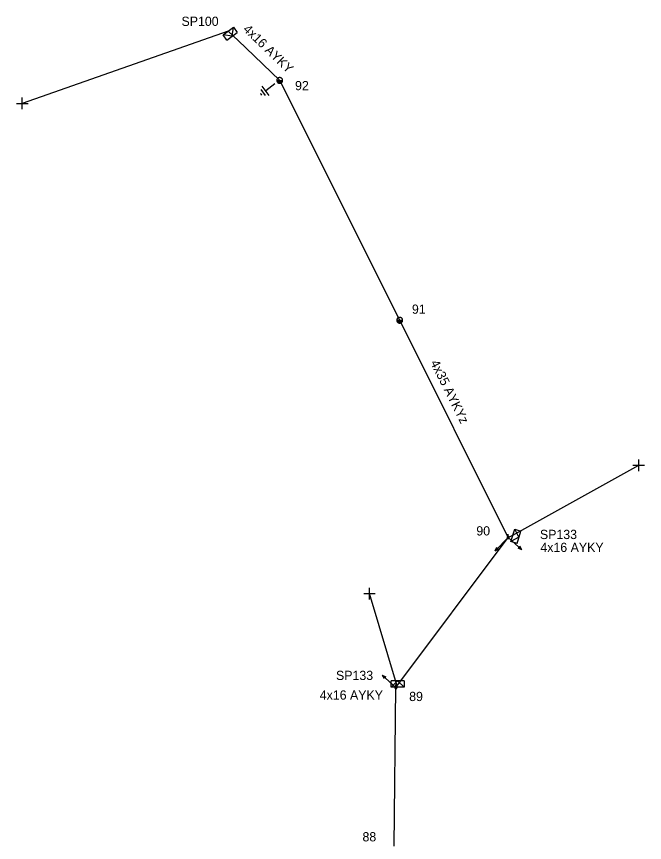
# Model space of a CAD drawing. Extents: x -788458 to -786145, y -1154772 to -1152372.
# Drawn here: x -787205.1 to -787137.1, y -1152461.7 to -1152372.4 of the extents above; entities that cross this region are included whole.
import ezdxf

# ---------------------------------------------------------------- set-up
doc = ezdxf.new("R2010")
doc.units = 0
for name, color, linetype in [('Vrstva 1', 7, 'Continuous'), ('Vrstva 13', 7, 'Continuous'), ('Vrstva 14', 7, 'Continuous'), ('Vrstva 15', 7, 'Continuous'), ('Vrstva 2', 7, 'Continuous'), ('Vrstva 31', 7, 'Continuous'), ('Vrstva 33', 7, 'Continuous'), ('Vrstva 34', 7, 'Continuous'), ('Vrstva 52', 7, 'Continuous'), ('Vrstva 53', 7, 'Continuous'), ('Vrstva 54', 7, 'Continuous'), ('Vrstva 59', 7, 'Continuous'), ('Vrstva 9', 7, 'Continuous')]:
    doc.layers.add(name, color=color, linetype=linetype)

# ---------------------------------------------------------------- blocks, each defined once
blk = doc.blocks.new('NN440')
at = {"layer": 'Vrstva 2'}
for points in [[(0.63, 0), (0.63, 0.06), (0.62, 0.13), (0.6, 0.19), (0.58, 0.25), (0.55, 0.31), (0.51, 0.37), (0.47, 0.42), (0.42, 0.46), (0.37, 0.51), (0.32, 0.54), (0.26, 0.57), (0.2, 0.59), (0.13, 0.61), (0.07, 0.62), (0, 0.63), (-0.06, 0.62), (-0.13, 0.61), (-0.19, 0.59), (-0.26, 0.57), (-0.31, 0.54), (-0.37, 0.51), (-0.42, 0.46), (-0.47, 0.42), (-0.51, 0.37), (-0.54, 0.31), (-0.57, 0.25), (-0.6, 0.19), (-0.62, 0.13), (-0.63, 0.06), (-0.63, 0), (-0.63, -0.07), (-0.62, -0.14), (-0.6, -0.2), (-0.57, -0.26), (-0.54, -0.32), (-0.51, -0.37), (-0.47, -0.43), (-0.42, -0.47), (-0.37, -0.51), (-0.31, -0.55), (-0.26, -0.58), (-0.19, -0.6), (-0.13, -0.62), (-0.06, -0.63), (0, -0.63), (0.07, -0.63), (0.13, -0.62), (0.2, -0.6), (0.26, -0.58), (0.32, -0.55), (0.37, -0.51), (0.42, -0.47), (0.47, -0.43), (0.51, -0.37), (0.55, -0.32), (0.58, -0.26), (0.6, -0.2), (0.62, -0.14), (0.63, -0.07), (0.63, 0)], [(-0.63, 0), (0.63, 0)], [(-0.6, -0.18), (0.57, -0.18)], [(-0.51, -0.32), (0.5, -0.32)], [(-0.37, -0.47), (0.35, -0.47)]]:
    blk.add_lwpolyline(points, dxfattribs=at)
blk = doc.blocks.new('NN560')
at = {"layer": 'Vrstva 2'}
for points in [[(1.999, -0.001), (1.59, 0.141)], [(0, -0.001), (1.999, -0.001)], [(1.999, -0.001), (1.59, -0.134)]]:
    blk.add_lwpolyline(points, dxfattribs=at)
blk = doc.blocks.new('NN800')
at = {"layer": 'Vrstva 1'}
for points in [[(-0.442, 0.442), (0.442, -0.442)], [(-0.442, -0.442), (0.442, 0.442)]]:
    blk.add_lwpolyline(points, dxfattribs=at)
blk = doc.blocks.new('NN630')
at = {"layer": 'Vrstva 9'}
for points in [[(-0.003, -0.7), (-0.703, 0)], [(-0.703, -0.7), (-0.703, 0), (0.697, 0), (0.697, -0.7)], [(-0.703, -0.7), (0.697, -0.7)], [(-0.003, -0.7), (0.697, 0)]]:
    blk.add_lwpolyline(points, dxfattribs=at)
blk = doc.blocks.new('NN810')
at = {"layer": 'Vrstva 14'}
for points in [[(0.004, -0.64), (0.004, -1.89)], [(0.629, -1.89), (-0.621, -1.89)], [(0.388, -2.2), (-0.399, -2.2)], [(0.004, -2.515), (-0.124, -2.515)], [(0.137, -2.515), (0.004, -2.515)]]:
    blk.add_lwpolyline(points, dxfattribs=at)
blk = doc.blocks.new('NN500')
at = {"layer": 'Vrstva 2'}
for points in [[(0, -0.24), (0.02, -0.23), (0.05, -0.23), (0.07, -0.22), (0.09, -0.22), (0.12, -0.2), (0.14, -0.19), (0.16, -0.18), (0.17, -0.16), (0.19, -0.14), (0.2, -0.12), (0.21, -0.1), (0.22, -0.07), (0.23, -0.05), (0.23, -0.02), (0.23, 0), (0.23, 0.02), (0.23, 0.05), (0.22, 0.07), (0.21, 0.1), (0.2, 0.12), (0.19, 0.14), (0.17, 0.16), (0.16, 0.17), (0.14, 0.19), (0.12, 0.2), (0.09, 0.21), (0.07, 0.22), (0.05, 0.23), (0.02, 0.23), (0, 0.23), (-0.03, 0.23), (-0.05, 0.23), (-0.07, 0.22), (-0.1, 0.21), (-0.12, 0.2), (-0.14, 0.19), (-0.16, 0.17), (-0.18, 0.16), (-0.19, 0.14), (-0.2, 0.12), (-0.22, 0.1), (-0.22, 0.07), (-0.23, 0.05), (-0.23, 0.02), (-0.24, 0), (-0.23, -0.02), (-0.23, -0.05), (-0.22, -0.07), (-0.22, -0.1), (-0.2, -0.12), (-0.19, -0.14), (-0.18, -0.16), (-0.16, -0.18), (-0.14, -0.19), (-0.12, -0.2), (-0.1, -0.22), (-0.07, -0.22), (-0.05, -0.23), (-0.03, -0.23), (0, -0.24)], [(0, -0.24), (0.02, -0.23), (0.05, -0.23), (0.07, -0.22), (0.09, -0.22), (0.12, -0.2), (0.14, -0.19), (0.16, -0.18), (0.17, -0.16), (0.19, -0.14), (0.2, -0.12), (0.21, -0.1), (0.22, -0.07), (0.23, -0.05), (0.23, -0.02), (0.23, 0), (0.23, 0.02), (0.23, 0.05), (0.22, 0.07), (0.21, 0.1), (0.2, 0.12), (0.19, 0.14), (0.17, 0.16), (0.16, 0.17), (0.14, 0.19), (0.12, 0.2), (0.09, 0.21), (0.07, 0.22), (0.05, 0.23), (0.02, 0.23), (0, 0.23), (-0.03, 0.23), (-0.05, 0.23), (-0.07, 0.22), (-0.1, 0.21), (-0.12, 0.2), (-0.14, 0.19), (-0.16, 0.17), (-0.18, 0.16), (-0.19, 0.14), (-0.2, 0.12), (-0.22, 0.1), (-0.22, 0.07), (-0.23, 0.05), (-0.23, 0.02), (-0.24, 0), (-0.23, -0.02), (-0.23, -0.05), (-0.22, -0.07), (-0.22, -0.1), (-0.2, -0.12), (-0.19, -0.14), (-0.18, -0.16), (-0.16, -0.18), (-0.14, -0.19), (-0.12, -0.2), (-0.1, -0.22), (-0.07, -0.22), (-0.05, -0.23), (-0.03, -0.23), (0, -0.24)], [(0, -0.21), (0.02, -0.2), (0.04, -0.2), (0.06, -0.2), (0.08, -0.19), (0.1, -0.18), (0.12, -0.17), (0.14, -0.15), (0.15, -0.14), (0.16, -0.12), (0.18, -0.1), (0.19, -0.08), (0.19, -0.06), (0.2, -0.04), (0.2, -0.02), (0.2, 0), (0.2, 0.02), (0.2, 0.04), (0.19, 0.06), (0.19, 0.08), (0.18, 0.1), (0.16, 0.12), (0.15, 0.14), (0.14, 0.15), (0.12, 0.17), (0.1, 0.18), (0.08, 0.19), (0.06, 0.19), (0.04, 0.2), (0.02, 0.2), (0, 0.2), (-0.02, 0.2), (-0.04, 0.2), (-0.06, 0.19), (-0.08, 0.19), (-0.1, 0.18), (-0.12, 0.17), (-0.14, 0.15), (-0.15, 0.14), (-0.17, 0.12), (-0.18, 0.1), (-0.19, 0.08), (-0.2, 0.06), (-0.2, 0.04), (-0.21, 0.02), (-0.21, 0), (-0.21, -0.02), (-0.2, -0.04), (-0.2, -0.06), (-0.19, -0.08), (-0.18, -0.1), (-0.17, -0.12), (-0.15, -0.14), (-0.14, -0.15), (-0.12, -0.17), (-0.1, -0.18), (-0.08, -0.19), (-0.06, -0.2), (-0.04, -0.2), (-0.02, -0.2), (0, -0.21)], [(0, -0.18), (0.02, -0.18), (0.04, -0.17), (0.05, -0.17), (0.07, -0.16), (0.09, -0.15), (0.1, -0.14), (0.12, -0.13), (0.13, -0.12), (0.14, -0.1), (0.15, -0.09), (0.16, -0.07), (0.17, -0.05), (0.17, -0.04), (0.17, -0.02), (0.17, 0), (0.17, 0.02), (0.17, 0.04), (0.17, 0.05), (0.16, 0.07), (0.15, 0.09), (0.14, 0.1), (0.13, 0.12), (0.12, 0.13), (0.1, 0.14), (0.09, 0.15), (0.07, 0.16), (0.05, 0.17), (0.04, 0.17), (0.02, 0.17), (0, 0.18), (-0.02, 0.17), (-0.04, 0.17), (-0.06, 0.17), (-0.07, 0.16), (-0.09, 0.15), (-0.1, 0.14), (-0.12, 0.13), (-0.13, 0.12), (-0.14, 0.1), (-0.15, 0.09), (-0.16, 0.07), (-0.17, 0.05), (-0.17, 0.04), (-0.18, 0.02), (-0.18, 0), (-0.18, -0.02), (-0.17, -0.04), (-0.17, -0.05), (-0.16, -0.07), (-0.15, -0.09), (-0.14, -0.1), (-0.13, -0.12), (-0.12, -0.13), (-0.1, -0.14), (-0.09, -0.15), (-0.07, -0.16), (-0.06, -0.17), (-0.04, -0.17), (-0.02, -0.18), (0, -0.18)], [(0, -0.15), (0.01, -0.15), (0.03, -0.14), (0.04, -0.14), (0.06, -0.13), (0.07, -0.13), (0.08, -0.12), (0.1, -0.11), (0.11, -0.1), (0.12, -0.09), (0.13, -0.07), (0.13, -0.06), (0.14, -0.05), (0.14, -0.03), (0.14, -0.02), (0.14, 0), (0.14, 0.01), (0.14, 0.03), (0.14, 0.04), (0.13, 0.06), (0.13, 0.07), (0.12, 0.09), (0.11, 0.1), (0.1, 0.11), (0.08, 0.12), (0.07, 0.13), (0.06, 0.13), (0.04, 0.14), (0.03, 0.14), (0.01, 0.14), (0, 0.15), (-0.02, 0.14), (-0.03, 0.14), (-0.05, 0.14), (-0.06, 0.13), (-0.07, 0.13), (-0.09, 0.12), (-0.1, 0.11), (-0.11, 0.1), (-0.12, 0.09), (-0.13, 0.07), (-0.13, 0.06), (-0.14, 0.04), (-0.14, 0.03), (-0.15, 0.01), (-0.15, 0), (-0.15, -0.02), (-0.14, -0.03), (-0.14, -0.05), (-0.13, -0.06), (-0.13, -0.07), (-0.12, -0.09), (-0.11, -0.1), (-0.1, -0.11), (-0.09, -0.12), (-0.07, -0.13), (-0.06, -0.13), (-0.05, -0.14), (-0.03, -0.14), (-0.02, -0.15), (0, -0.15)], [(0, -0.12), (0.01, -0.12), (0.02, -0.11), (0.03, -0.11), (0.05, -0.11), (0.06, -0.1), (0.07, -0.09), (0.08, -0.09), (0.09, -0.08), (0.09, -0.07), (0.1, -0.06), (0.11, -0.05), (0.11, -0.04), (0.11, -0.02), (0.11, -0.01), (0.12, 0), (0.11, 0.01), (0.11, 0.02), (0.11, 0.04), (0.11, 0.05), (0.1, 0.06), (0.09, 0.07), (0.09, 0.08), (0.08, 0.09), (0.07, 0.09), (0.06, 0.1), (0.05, 0.11), (0.03, 0.11), (0.02, 0.11), (0.01, 0.12), (0, 0.12), (-0.01, 0.12), (-0.03, 0.11), (-0.04, 0.11), (-0.05, 0.11), (-0.06, 0.1), (-0.07, 0.09), (-0.08, 0.09), (-0.09, 0.08), (-0.1, 0.07), (-0.1, 0.06), (-0.11, 0.05), (-0.11, 0.04), (-0.12, 0.02), (-0.12, 0.01), (-0.12, 0), (-0.12, -0.01), (-0.12, -0.02), (-0.11, -0.04), (-0.11, -0.05), (-0.1, -0.06), (-0.1, -0.07), (-0.09, -0.08), (-0.08, -0.09), (-0.07, -0.09), (-0.06, -0.1), (-0.05, -0.11), (-0.04, -0.11), (-0.03, -0.11), (-0.01, -0.12), (0, -0.12)], [(0, -0.09), (0.01, -0.09), (0.02, -0.09), (0.03, -0.08), (0.03, -0.08), (0.04, -0.08), (0.05, -0.07), (0.06, -0.07), (0.06, -0.06), (0.07, -0.05), (0.07, -0.04), (0.08, -0.04), (0.08, -0.03), (0.08, -0.02), (0.09, -0.01), (0.09, 0), (0.09, 0.01), (0.08, 0.02), (0.08, 0.03), (0.08, 0.03), (0.07, 0.04), (0.07, 0.05), (0.06, 0.06), (0.06, 0.06), (0.05, 0.07), (0.04, 0.07), (0.03, 0.08), (0.03, 0.08), (0.02, 0.08), (0.01, 0.09), (0, 0.09), (-0.01, 0.09), (-0.02, 0.08), (-0.03, 0.08), (-0.04, 0.08), (-0.04, 0.07), (-0.05, 0.07), (-0.06, 0.06), (-0.07, 0.06), (-0.07, 0.05), (-0.08, 0.04), (-0.08, 0.03), (-0.08, 0.03), (-0.09, 0.02), (-0.09, 0.01), (-0.09, 0), (-0.09, -0.01), (-0.09, -0.02), (-0.08, -0.03), (-0.08, -0.04), (-0.08, -0.04), (-0.07, -0.05), (-0.07, -0.06), (-0.06, -0.07), (-0.05, -0.07), (-0.04, -0.08), (-0.04, -0.08), (-0.03, -0.08), (-0.02, -0.09), (-0.01, -0.09), (0, -0.09)], [(0, -0.06), (0, -0.06), (0.01, -0.06), (0.02, -0.05), (0.02, -0.05), (0.03, -0.05), (0.03, -0.05), (0.04, -0.04), (0.04, -0.04), (0.05, -0.03), (0.05, -0.03), (0.05, -0.02), (0.05, -0.02), (0.05, -0.01), (0.06, -0.01), (0.06, 0), (0.06, 0.01), (0.05, 0.01), (0.05, 0.02), (0.05, 0.02), (0.05, 0.03), (0.05, 0.03), (0.04, 0.04), (0.04, 0.04), (0.03, 0.05), (0.03, 0.05), (0.02, 0.05), (0.02, 0.05), (0.01, 0.06), (0, 0.06), (0, 0.06), (-0.01, 0.06), (-0.01, 0.06), (-0.02, 0.05), (-0.02, 0.05), (-0.03, 0.05), (-0.03, 0.05), (-0.04, 0.04), (-0.04, 0.04), (-0.05, 0.03), (-0.05, 0.03), (-0.05, 0.02), (-0.06, 0.02), (-0.06, 0.01), (-0.06, 0.01), (-0.06, 0), (-0.06, -0.01), (-0.06, -0.01), (-0.06, -0.02), (-0.05, -0.02), (-0.05, -0.03), (-0.05, -0.03), (-0.04, -0.04), (-0.04, -0.04), (-0.03, -0.05), (-0.03, -0.05), (-0.02, -0.05), (-0.02, -0.05), (-0.01, -0.06), (-0.01, -0.06), (0, -0.06)], [(0, -0.03), (0, -0.03), (0, -0.03), (0.01, -0.03), (0.01, -0.03), (0.01, -0.02), (0.02, -0.02), (0.02, -0.02), (0.02, -0.02), (0.02, -0.02), (0.02, -0.01), (0.02, -0.01), (0.03, -0.01), (0.03, -0.01), (0.03, 0), (0.03, 0), (0.03, 0), (0.03, 0.01), (0.03, 0.01), (0.02, 0.01), (0.02, 0.01), (0.02, 0.02), (0.02, 0.02), (0.02, 0.02), (0.02, 0.02), (0.01, 0.02), (0.01, 0.02), (0.01, 0.03), (0, 0.03), (0, 0.03), (0, 0.03), (0, 0.03), (-0.01, 0.03), (-0.01, 0.03), (-0.01, 0.02), (-0.02, 0.02), (-0.02, 0.02), (-0.02, 0.02), (-0.02, 0.02), (-0.02, 0.02), (-0.03, 0.01), (-0.03, 0.01), (-0.03, 0.01), (-0.03, 0.01), (-0.03, 0), (-0.03, 0), (-0.03, 0), (-0.03, -0.01), (-0.03, -0.01), (-0.03, -0.01), (-0.03, -0.01), (-0.02, -0.02), (-0.02, -0.02), (-0.02, -0.02), (-0.02, -0.02), (-0.02, -0.02), (-0.01, -0.03), (-0.01, -0.03), (-0.01, -0.03), (0, -0.03), (0, -0.03)], [(0.23, 0), (0.7, 0)]]:
    blk.add_lwpolyline(points, dxfattribs=at)

msp = doc.modelspace()

# ---------------------------------------------------------------- linework, layer by layer
at = {"layer": 'Vrstva 52'}
for points in [[(-787176.59, -1152379.26), (-787180.251, -1152375.744), (-787181.056, -1152374.971), (-787182.15, -1152373.92)], [(-787164.2, -1152462.08), (-787164.02, -1152444.92), (-787151.88, -1152428.69), (-787163.61, -1152405.19), (-787176.59, -1152379.26)], [(-787151.88, -1152428.69), (-787151.37, -1152428.45)], [(-787164.02, -1152444.92), (-787163.84, -1152444.88)]]:
    msp.add_lwpolyline(points, dxfattribs=at)
at = {"layer": 'Vrstva 59'}
for points in [[(-787182.15, -1152373.92), (-787204.44, -1152381.75)], [(-787151.37, -1152428.45), (-787137.75, -1152420.88)], [(-787163.84, -1152444.88), (-787166.88, -1152434.75)]]:
    msp.add_lwpolyline(points, dxfattribs=at)

# ---------------------------------------------------------------- block references
at = {"layer": 'Vrstva 13', "xscale": 0.5, "yscale": 0.5}
for p in [(-787176.59, -1152379.26), (-787163.61, -1152405.19)]:
    msp.add_blockref('NN440', p, dxfattribs=at)
at = {"layer": 'Vrstva 13', "xscale": 0.5, "yscale": 0.5, "rotation": 90}
for p in [(-787151.88, -1152428.69), (-787164.02, -1152444.92)]:
    msp.add_blockref('NN500', p, dxfattribs=at)
at = {"layer": 'Vrstva 13'}
for p, rotation in [((-787151.88, -1152428.69), -134.17845556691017), ((-787151.88, -1152428.69), -41.490708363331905), ((-787164.02, -1152444.92), 137.29577778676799)]:
    msp.add_blockref('NN560', p, dxfattribs=dict(at, rotation=rotation))
at = {"layer": 'Vrstva 15', "rotation": -53.37803328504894}
msp.add_blockref('NN810', (-787176.59, -1152379.26), dxfattribs=at)
at = {"layer": 'Vrstva 31'}
for p, rotation in [((-787182.15, -1152373.92), 35.32759878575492), ((-787151.37, -1152428.45), 72.85965069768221), ((-787163.84, -1152444.88), 180)]:
    msp.add_blockref('NN630', p, dxfattribs=dict(at, rotation=rotation))
at = {"layer": 'Vrstva 34'}
for p, rotation in [((-787204.44, -1152381.75), 44.99999995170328), ((-787137.75, -1152420.88), 45), ((-787166.88, -1152434.75), 45)]:
    msp.add_blockref('NN800', p, dxfattribs=dict(at, rotation=rotation))

# ---------------------------------------------------------------- texts
at = {"layer": 'Vrstva 14'}
for s, p in [('92', (-787174.929, -1152380.323)), ('91', (-787162.287, -1152404.494)), ('90', (-787155.318, -1152428.467)), ('89', (-787162.584, -1152446.373)), ('88', (-787167.634, -1152461.549))]:
    msp.add_text(s, height=1, dxfattribs=at).set_placement(p)
at = {"layer": 'Vrstva 33'}
for s, p in [('SP100', (-787187.215, -1152373.365)), ('SP133', (-787148.439, -1152428.855)), ('SP133', (-787170.499, -1152444.097))]:
    msp.add_text(s, height=1, dxfattribs=at).set_placement(p)
at = {"layer": 'Vrstva 53'}
msp.add_text('4x35 AYKYz', height=1, rotation=296.526, dxfattribs=at).set_placement((-787160.324, -1152409.776))
at = {"layer": 'Vrstva 54'}
msp.add_text('4x16 AYKY', height=1, rotation=316.156, dxfattribs=at).set_placement((-787180.629, -1152373.821))
for p in [(-787148.387, -1152430.252), (-787172.257, -1152446.218)]:
    msp.add_text('4x16 AYKY', height=1, dxfattribs=at).set_placement(p)

doc.saveas('drawing.dxf')
